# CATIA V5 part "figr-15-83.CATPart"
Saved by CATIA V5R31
Part number: Part1
Bounding box of the stored display mesh (mm): x 0 to 27, y -46 to 46, z -30 to 30
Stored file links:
  D:\PROJECTS\Project 2021\US EDITION\CATIA V5 6R 2021\Resources\Part Files\c15_catia_v5_6r2021_prt\figr-15-83.CATPart
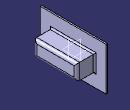
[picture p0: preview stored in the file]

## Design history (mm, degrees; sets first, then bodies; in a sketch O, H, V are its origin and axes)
SheetMetalParameters1: Thickness 2, BendRadius 4, KFactor 0.400515 {= log(min(100,max(20*SheetMetalParameters1.BendRadius,SheetMetalParameters1.Thickness)/SheetMetalParameters1.Thickness))/log(100)/2}, ReliefRadialLength 1, ReliefAxialLength 2, MinimumBendRadius 0
Body1 (main body)
  Sketch1 on yz-plane, origin (0, 0, 0), H (0, 1, 0), V (0, 0, 1)
    line L1 (46, 30) -> (46, -30)
    line L2 (46, -30) -> (-46, -30)
    line L3 (-46, -30) -> (-46, 30)
    line L4 (-46, 30) -> (46, 30)
    vertical: L1 V, L3 V
    horizontal: L2 H, L4 H
    equidistance: L1 L3 O, L2 L4 O
  Wall1: Thickness 2, Profile Sketch1, OffsetValue 0
  Sketch2 on face of Wall1, origin (2, 0, 0), H (0, 1, 0), V (0, 0, 1)
    line L1 (28, 9) -> (28, -9)
    line L2 (28, -9) -> (-28, -9)
    line L3 (-28, -9) -> (-28, 9)
    line L4 (-28, 9) -> (28, 9)
    vertical: L1 V, L3 V
    horizontal: L2 H, L4 H
    equidistance: L1 L3 O, L2 L4 O
  d_Stamp1: NewRoot_AttribNormalisation "No Standard", Stamp_FilletRadius 2, Stamp_IntersectFilletRadius 2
